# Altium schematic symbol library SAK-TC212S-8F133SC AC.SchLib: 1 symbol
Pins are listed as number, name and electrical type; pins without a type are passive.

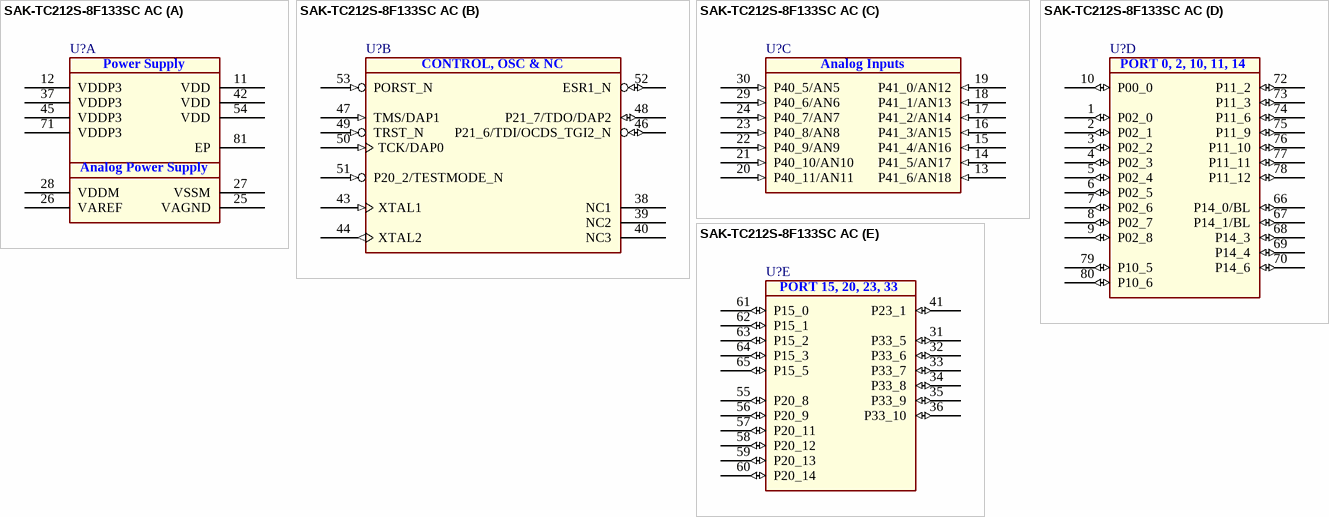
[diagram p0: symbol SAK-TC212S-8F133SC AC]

## SAK-TC212S-8F133SC AC
designator U?  (value not drawn)
32-Bit Single-Chip Microcontroller; Manufacturer: Infineon Technologies
part A pins: 11 VDD (power), 12 VDDP3 (power), 25 VAGND (power), 26 VAREF (power), 27 VSSM (power), 28 VDDM (power), 37 VDDP3 (power), 42 VDD (power), 45 VDDP3 (power), 54 VDD (power), 71 VDDP3 (power), 81 EP (power)
part B pins: 38 NC1, 39 NC2, 40 NC3, 43 XTAL1 (in), 44 XTAL2 (out), 46 P21_6/TDI/OCDS_TGI2_N (io), 47 TMS/DAP1 (in), 48 P21_7/TDO/DAP2 (io), 49 TRST_N (in), 50 TCK/DAP0 (in), 51 P20_2/TESTMODE_N (in), 52 ESR1_N (io), 53 PORST_N (in)
part C pins: 13 P41_6/AN18 (in), 14 P41_5/AN17 (in), 15 P41_4/AN16 (in), 16 P41_3/AN15 (in), 17 P41_2/AN14 (in), 18 P41_1/AN13 (in), 19 P41_0/AN12 (in), 20 P40_11/AN11 (in), 21 P40_10/AN10 (in), 22 P40_9/AN9 (in), 23 P40_8/AN8 (in), 24 P40_7/AN7 (in), 29 P40_6/AN6 (in), 30 P40_5/AN5 (in)
part D pins: 1 P02_0 (io), 2 P02_1 (io), 3 P02_2 (io), 4 P02_3 (io), 5 P02_4 (io), 6 P02_5 (io), 7 P02_6 (io), 8 P02_7 (io), 9 P02_8 (io), 10 P00_0 (io), 66 P14_0/BL (io), 67 P14_1/BL (io), 68 P14_3 (io), 69 P14_4 (io), 70 P14_6 (io), 72 P11_2 (io), 73 P11_3 (io), 74 P11_6 (io), 75 P11_9 (io), 76 P11_10 (io), 77 P11_11 (io), 78 P11_12 (io), 79 P10_5 (io), 80 P10_6 (io)
part E pins: 31 P33_5 (io), 32 P33_6 (io), 33 P33_7 (io), 34 P33_8 (io), 35 P33_9 (io), 36 P33_10 (io), 41 P23_1 (io), 55 P20_8 (io), 56 P20_9 (io), 57 P20_11 (io), 58 P20_12 (io), 59 P20_13 (io), 60 P20_14 (io), 61 P15_0 (io), 62 P15_1 (io), 63 P15_2 (io), 64 P15_3 (io), 65 P15_5 (io)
